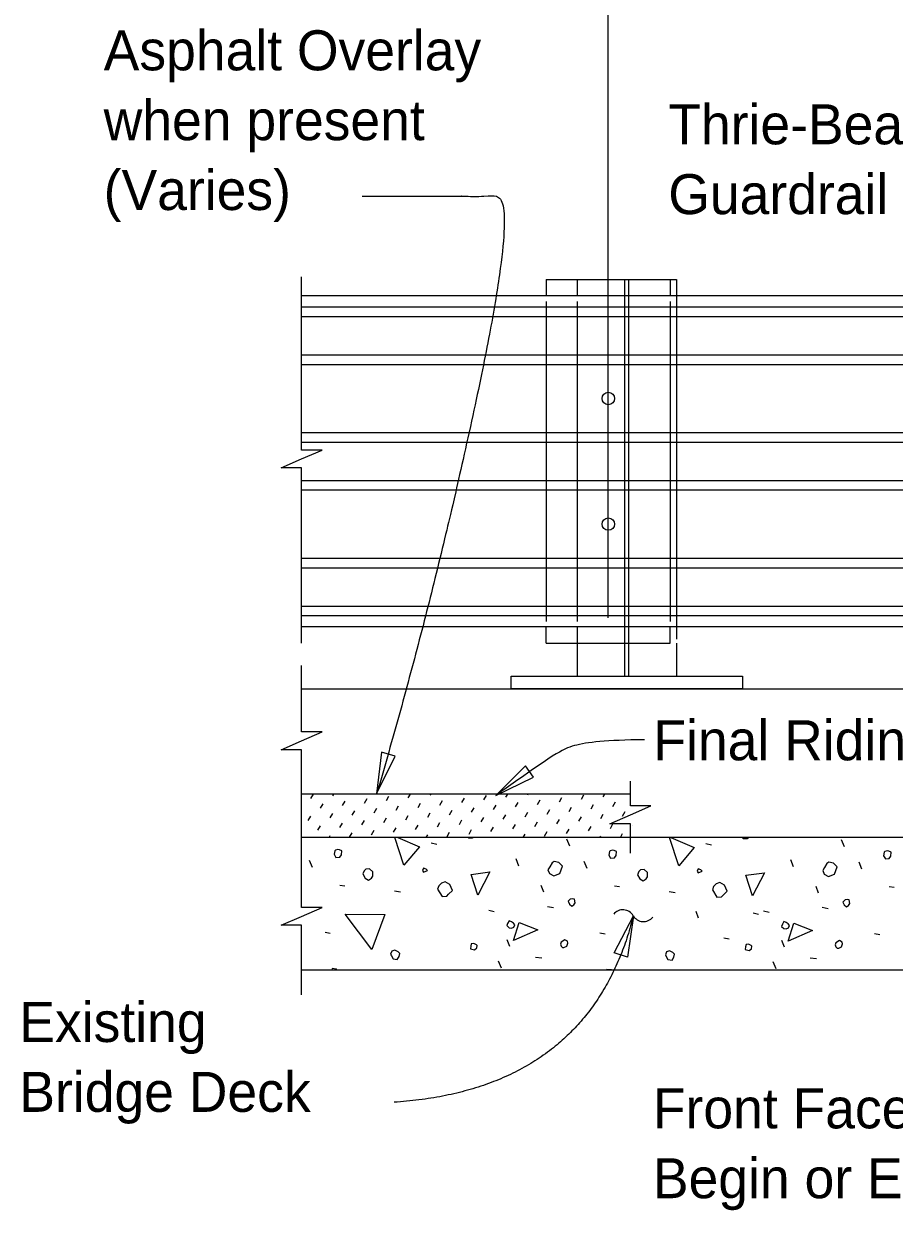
# Model space of a CAD drawing. Extents: x 21587 to 21659.1, y 56113.9 to 56155.9.
# Drawn here: x 21605.91 to 21610.3, y 56132.17 to 56138.15 of the extents above; entities that cross this region are included whole.
import ezdxf

# ---------------------------------------------------------------- set-up
doc = ezdxf.new("R2010")
doc.units = 0
for name, color, linetype in [('AdhocPoint_dp', 7, 'Continuous'), ('Border', 7, 'Continuous'), ('Patterning', 7, 'Continuous'), ('PlotBorder_dp', 7, 'Continuous'), ('SheetBorder_dp', 7, 'Continuous'), ('TextMisc', 7, 'Continuous')]:
    doc.layers.add(name, color=color, linetype=linetype)

msp = doc.modelspace()

# ---------------------------------------------------------------- linework, layer by layer
at = {"layer": 'AdhocPoint_dp'}
for p, q in [((21607.3117, 56134.8009), (21613.4854, 56134.8009)), ((21608.9696, 56134.2699), (21607.3116, 56134.2699)), ((21613.4854, 56134.0509), (21607.3117, 56134.0509)), ((21607.3117, 56133.3843), (21613.4854, 56133.3843))]:
    msp.add_line(p, q, dxfattribs=at)
at = {"layer": 'Border'}
for p, q in [((21608.7018, 56136.8635), (21609.2018, 56136.8635)), ((21608.7018, 56136.8635), (21608.7018, 56136.7802)), ((21619.5663, 56136.7801), (21607.3117, 56136.7801)), ((21607.3117, 56136.7246), (21619.5663, 56136.7246)), ((21607.3117, 56136.6764), (21619.5663, 56136.6764)), ((21607.3117, 56136.4835), (21619.5663, 56136.4835)), ((21607.3117, 56136.4353), (21619.5663, 56136.4353)), ((21607.3117, 56136.0914), (21619.5663, 56136.0914)), ((21607.3117, 56136.0431), (21619.5663, 56136.0431)), ((21607.3117, 56135.8503), (21619.5663, 56135.8503)), ((21607.3117, 56135.8022), (21619.5663, 56135.8022)), ((21607.3117, 56135.4582), (21619.5663, 56135.4582)), ((21607.3117, 56135.41), (21619.5663, 56135.41)), ((21607.3117, 56135.2172), (21619.5663, 56135.2172)), ((21607.3117, 56135.169), (21619.5663, 56135.169)), ((21619.5663, 56135.1134), (21607.3117, 56135.1134)), ((21608.7018, 56135.1135), (21608.7018, 56134.8635)), ((21609.2018, 56135.0302), (21609.2018, 56134.8635)), ((21608.3685, 56134.8635), (21609.5351, 56134.8635)), ((21608.3685, 56134.801), (21608.3685, 56134.8635)), ((21608.7018, 56134.8635), (21609.2018, 56134.8635)), ((21609.5351, 56134.8635), (21609.5351, 56134.801)), ((21608.3685, 56134.801), (21609.5351, 56134.801))]:
    msp.add_line(p, q, dxfattribs=at)
for centre in [(21608.858, 56136.2634), (21608.858, 56135.6303)]:
    msp.add_circle(centre, 0.0312, dxfattribs=at)
at = {"layer": 'Patterning'}
for p, q in [((21608.9414, 56134.8635), (21608.9414, 56136.8635)), ((21608.9622, 56134.8635), (21608.9622, 56136.8635)), ((21609.2018, 56136.8635), (21609.2018, 56135.0505)), ((21608.7018, 56136.7516), (21608.7018, 56135.1398))]:
    msp.add_line(p, q, dxfattribs=at)
at = {"layer": 'PlotBorder_dp'}
msp.add_line((21608.858, 56135.1577), (21608.858, 56143.2258), dxfattribs=at)
for points in [[(21607.3117, 56135.0303), (21607.3117, 56135.9135), (21607.2084, 56135.9135), (21607.3117, 56135.9585), (21607.4151, 56136.0035), (21607.3117, 56136.0035), (21607.3117, 56136.8765)], [(21607.3117, 56134.0229), (21607.3117, 56134.493), (21607.2084, 56134.493), (21607.3117, 56134.538), (21607.4151, 56134.583), (21607.3117, 56134.583), (21607.3117, 56134.9175)], [(21608.9697, 56133.972), (21608.9697, 56134.1198), (21608.8664, 56134.1198), (21608.9697, 56134.1648), (21609.073, 56134.2098), (21608.9697, 56134.2098), (21608.9697, 56134.3343)], [(21607.3117, 56133.2578), (21607.3117, 56133.6084), (21607.2084, 56133.6084), (21607.3117, 56133.6534), (21607.4151, 56133.6984), (21607.3117, 56133.6984), (21607.3117, 56134.0229)]]:
    msp.add_lwpolyline(points, dxfattribs=at)
for points in [[(21607.6902, 56134.2707), (21607.7828, 56134.4606), (21607.7151, 56134.4805)], [(21608.2911, 56134.2633), (21608.4817, 56134.3543), (21608.4411, 56134.412)], [(21608.9843, 56133.6565), (21608.9539, 56133.4475), (21608.8867, 56133.4692)]]:
    msp.add_lwpolyline(points, close=True, dxfattribs=at)
for centre, start, end in [((21608.9319, 56133.6269), 30.00813, 141.73535), ((21609.0352, 56133.6865), 210.00813, 321.73535)]:
    msp.add_arc(centre, 0.0596, start, end, dxfattribs=at)
for points, degree in [([(21607.6165, 56137.2827), (21608.1708, 56137.2827), (21608.4111, 56137.2827), (21607.9729, 56135.2323), (21607.6902, 56134.2708)], 2), ([(21609.0397, 56134.5436), (21608.8463, 56134.5415), (21608.6579, 56134.5211), (21608.5865, 56134.4713), (21608.2911, 56134.2634)], 3), ([(21608.9843, 56133.6565), (21608.7637, 56132.7828), (21607.778, 56132.7162)], 2)]:
    msp.add_open_spline(points, degree=degree, dxfattribs=at)
at = {"layer": 'TextMisc'}
for p, q in [((21608.5455, 56136.8635), (21609.1705, 56136.8635)), ((21608.5455, 56136.8635), (21608.5455, 56136.7802)), ((21609.1705, 56136.8635), (21609.1705, 56136.7802)), ((21608.5455, 56136.7516), (21608.5455, 56135.1398)), ((21609.1705, 56136.7516), (21609.1705, 56135.1398)), ((21608.5455, 56135.0302), (21608.5455, 56135.1135)), ((21609.1705, 56135.0302), (21609.1705, 56135.1135)), ((21608.5455, 56135.0302), (21609.1705, 56135.0302)), ((21607.3586, 56134.2474), (21607.3715, 56134.2698)), ((21607.4692, 56134.2604), (21607.4747, 56134.2699)), ((21607.8499, 56134.2504), (21607.8612, 56134.2699)), ((21607.9606, 56134.2634), (21607.9643, 56134.2699)), ((21608.3413, 56134.2535), (21608.3508, 56134.2699)), ((21608.4519, 56134.2664), (21608.4539, 56134.2699)), ((21608.722, 56134.2435), (21608.735, 56134.2659)), ((21608.8327, 56134.2565), (21608.8404, 56134.2699)), ((21608.9433, 56134.2695), (21608.9436, 56134.2699)), ((21607.4074, 56134.1986), (21607.4204, 56134.221)), ((21607.518, 56134.2116), (21607.531, 56134.234)), ((21607.6287, 56134.2245), (21607.6416, 56134.2469)), ((21607.7393, 56134.2375), (21607.7523, 56134.2599)), ((21607.7881, 56134.1887), (21607.8011, 56134.211)), ((21607.8988, 56134.2016), (21607.9117, 56134.224)), ((21608.0094, 56134.2146), (21608.0224, 56134.237)), ((21608.12, 56134.2275), (21608.133, 56134.2499)), ((21608.2307, 56134.2405), (21608.2436, 56134.2629)), ((21608.2795, 56134.1917), (21608.2925, 56134.2141)), ((21608.3901, 56134.2046), (21608.4031, 56134.227)), ((21608.5008, 56134.2176), (21608.5137, 56134.24)), ((21608.6114, 56134.2306), (21608.6244, 56134.253)), ((21608.6602, 56134.1817), (21608.6732, 56134.2041)), ((21608.7709, 56134.1947), (21608.7838, 56134.2171)), ((21608.8815, 56134.2077), (21608.8945, 56134.23)), ((21607.3456, 56134.1368), (21607.3586, 56134.1592)), ((21607.4562, 56134.1498), (21607.4692, 56134.1722)), ((21607.5669, 56134.1627), (21607.5798, 56134.1851)), ((21607.6775, 56134.1757), (21607.6905, 56134.1981)), ((21607.7263, 56134.1269), (21607.7393, 56134.1492)), ((21607.837, 56134.1398), (21607.8499, 56134.1622)), ((21607.9476, 56134.1528), (21607.9606, 56134.1752)), ((21608.0582, 56134.1657), (21608.0712, 56134.1881)), ((21608.1689, 56134.1787), (21608.1818, 56134.2011)), ((21608.2177, 56134.1299), (21608.2307, 56134.1523)), ((21608.3283, 56134.1428), (21608.3413, 56134.1652)), ((21608.439, 56134.1558), (21608.4519, 56134.1782)), ((21608.5496, 56134.1688), (21608.5626, 56134.1912)), ((21608.7091, 56134.1329), (21608.722, 56134.1553)), ((21608.8197, 56134.1459), (21608.8327, 56134.1682)), ((21608.9303, 56134.1588), (21608.9433, 56134.1812)), ((21607.3944, 56134.088), (21607.4074, 56134.1104)), ((21607.5051, 56134.1009), (21607.518, 56134.1233)), ((21607.6157, 56134.1139), (21607.6287, 56134.1363)), ((21607.6645, 56134.0651), (21607.6775, 56134.0874)), ((21607.7752, 56134.078), (21607.7881, 56134.1004)), ((21607.8858, 56134.091), (21607.8988, 56134.1134)), ((21607.9964, 56134.1039), (21608.0094, 56134.1263)), ((21608.1071, 56134.1169), (21608.12, 56134.1393)), ((21608.1559, 56134.0681), (21608.1689, 56134.0905)), ((21608.2665, 56134.081), (21608.2795, 56134.1034)), ((21608.3772, 56134.094), (21608.3901, 56134.1164)), ((21608.4878, 56134.107), (21608.5008, 56134.1294)), ((21608.5984, 56134.1199), (21608.6114, 56134.1423)), ((21608.6473, 56134.0711), (21608.6602, 56134.0935)), ((21608.7579, 56134.0841), (21608.7709, 56134.1065)), ((21608.8685, 56134.097), (21608.8815, 56134.1194)), ((21608.9792, 56134.11), (21608.9793, 56134.1102)), ((21607.4501, 56134.0509), (21607.4562, 56134.0615)), ((21607.5539, 56134.0521), (21607.5669, 56134.0745)), ((21607.8366, 56134.0509), (21607.837, 56134.0516)), ((21607.9397, 56134.0509), (21607.9476, 56134.0645)), ((21608.0453, 56134.0551), (21608.0582, 56134.0775)), ((21608.3262, 56134.0509), (21608.3283, 56134.0546)), ((21608.4293, 56134.0509), (21608.439, 56134.0676)), ((21608.5366, 56134.0581), (21608.5496, 56134.0805)), ((21608.6635, 56134.0079), (21608.6494, 56134.0432)), ((21608.8158, 56134.0509), (21608.8197, 56134.0576)), ((21608.919, 56134.0509), (21608.9303, 56134.0706)), ((21610.0482, 56134.0043), (21610.034, 56134.0397)), ((21607.9652, 56134.0238), (21607.9935, 56134.0167)), ((21609.3499, 56134.0203), (21609.3782, 56134.0132)), ((21607.3666, 56133.8989), (21607.3524, 56133.9343)), ((21608.4072, 56133.9071), (21608.393, 56133.9425)), ((21608.7513, 56133.8954), (21608.7371, 56133.9307)), ((21609.7919, 56133.9036), (21609.7777, 56133.9389)), ((21610.1359, 56133.8918), (21610.1218, 56133.9272)), ((21607.5045, 56133.8105), (21607.5292, 56133.807)), ((21608.5327, 56133.7745), (21608.5203, 56133.8081)), ((21608.8892, 56133.807), (21608.9139, 56133.8034)), ((21609.9174, 56133.771), (21609.905, 56133.8046)), ((21610.2738, 56133.8034), (21610.2986, 56133.7999)), ((21607.7802, 56133.7822), (21607.8103, 56133.7769)), ((21609.1649, 56133.7787), (21609.195, 56133.7734)), ((21608.2552, 56133.6844), (21608.2834, 56133.6773)), ((21608.5515, 56133.7027), (21608.5816, 56133.6974)), ((21609.3134, 56133.6443), (21609.301, 56133.6779)), ((21609.5874, 56133.6709), (21609.6157, 56133.6638)), ((21609.6398, 56133.6808), (21609.6681, 56133.6738)), ((21609.9362, 56133.6991), (21609.9662, 56133.6938)), ((21607.4302, 56133.5736), (21607.4567, 56133.5683)), ((21608.8149, 56133.5701), (21608.8414, 56133.5648)), ((21610.1996, 56133.5666), (21610.2261, 56133.5613)), ((21608.3612, 56133.5018), (21608.3488, 56133.5354)), ((21609.4407, 56133.5453), (21609.4672, 56133.54)), ((21609.7459, 56133.4982), (21609.7335, 56133.5318)), ((21608.3188, 56133.3922), (21608.3046, 56133.4275)), ((21608.4914, 56133.4481), (21608.5232, 56133.4446)), ((21609.8761, 56133.4446), (21609.9079, 56133.4411)), ((21609.7035, 56133.3886), (21609.6893, 56133.424))]:
    msp.add_line(p, q, dxfattribs=at)
for points in [[(21607.828, 56133.9113), (21607.7825, 56134.0509)], [(21607.7964, 56134.0509), (21607.9058, 56134.0032), (21607.828, 56133.9113)], [(21608.1516, 56134.0509), (21608.1526, 56134.0485), (21608.1502, 56134.0509)], [(21608.1526, 56134.0485), (21608.1738, 56134.0485), (21608.1762, 56134.0509)], [(21609.2127, 56133.9077), (21609.1661, 56134.0509)], [(21609.173, 56134.0509), (21609.2904, 56133.9997), (21609.2127, 56133.9077)], [(21609.5348, 56134.0509), (21609.5373, 56134.045), (21609.5338, 56134.0485)], [(21609.5373, 56134.045), (21609.5585, 56134.045), (21609.5644, 56134.0509)], [(21607.4762, 56133.9661), (21607.485, 56133.9502), (21607.5045, 56133.9519), (21607.5133, 56133.9643), (21607.5151, 56133.9838), (21607.5027, 56133.9891), (21607.4939, 56133.9908), (21607.4833, 56133.9873), (21607.4797, 56133.9838), (21607.4762, 56133.9661)], [(21608.8609, 56133.9625), (21608.8697, 56133.9466), (21608.8892, 56133.9484), (21608.898, 56133.9608), (21608.8998, 56133.9802), (21608.8874, 56133.9855), (21608.8785, 56133.9873), (21608.8679, 56133.9838), (21608.8644, 56133.9802), (21608.8609, 56133.9625)], [(21610.2455, 56133.959), (21610.2544, 56133.9431), (21610.2738, 56133.9449), (21610.2827, 56133.9572), (21610.2844, 56133.9767), (21610.2721, 56133.982), (21610.2632, 56133.9838), (21610.2526, 56133.9802), (21610.2491, 56133.9767), (21610.2455, 56133.959)], [(21608.561, 56133.87), (21608.584, 56133.8576), (21608.614, 56133.87), (21608.6264, 56133.9071), (21608.6087, 56133.9248), (21608.5857, 56133.9301), (21608.5751, 56133.923), (21608.5627, 56133.9036), (21608.5539, 56133.8877), (21608.561, 56133.87)], [(21609.9457, 56133.8665), (21609.9686, 56133.8541), (21609.9987, 56133.8665), (21610.0111, 56133.9036), (21609.9934, 56133.9213), (21609.9704, 56133.9266), (21609.9598, 56133.9195), (21609.9474, 56133.9), (21609.9386, 56133.8841), (21609.9457, 56133.8665)], [(21607.6211, 56133.8671), (21607.6318, 56133.8459), (21607.6494, 56133.8353), (21607.6636, 56133.8459), (21607.6706, 56133.8565), (21607.6706, 56133.8777), (21607.6547, 56133.8936), (21607.6353, 56133.8918), (21607.6265, 56133.883), (21607.6211, 56133.8671)], [(21607.927, 56133.8759), (21607.9464, 56133.8848), (21607.9393, 56133.8918), (21607.927, 56133.8971), (21607.9217, 56133.8848), (21607.927, 56133.8759)], [(21608.2003, 56133.7604), (21608.1668, 56133.8647), (21608.2605, 56133.8771), (21608.2003, 56133.7604)], [(21609.0058, 56133.8635), (21609.0164, 56133.8423), (21609.0341, 56133.8317), (21609.0483, 56133.8423), (21609.0553, 56133.8529), (21609.0553, 56133.8742), (21609.0394, 56133.8901), (21609.02, 56133.8883), (21609.0111, 56133.8795), (21609.0058, 56133.8635)], [(21609.3116, 56133.8724), (21609.3311, 56133.8812), (21609.324, 56133.8883), (21609.3116, 56133.8936), (21609.3063, 56133.8812), (21609.3116, 56133.8724)], [(21609.585, 56133.7569), (21609.5514, 56133.8612), (21609.6451, 56133.8735), (21609.585, 56133.7569)], [(21607.9977, 56133.7911), (21608.0207, 56133.7539), (21608.0436, 56133.7557), (21608.0525, 56133.7646), (21608.0719, 56133.784), (21608.0596, 56133.814), (21608.0348, 56133.8282), (21608.0171, 56133.8211), (21608.003, 56133.807), (21607.9977, 56133.7911)], [(21609.3824, 56133.7875), (21609.4053, 56133.7504), (21609.4283, 56133.7522), (21609.4372, 56133.761), (21609.4566, 56133.7805), (21609.4442, 56133.8105), (21609.4195, 56133.8247), (21609.4018, 56133.8176), (21609.3877, 56133.8034), (21609.3824, 56133.7875)], [(21608.6629, 56133.7151), (21608.6735, 56133.7044), (21608.6841, 56133.7115), (21608.6912, 56133.7221), (21608.6876, 56133.7398), (21608.6788, 56133.7416), (21608.6664, 56133.7398), (21608.6558, 56133.7292), (21608.6629, 56133.7151)], [(21610.0476, 56133.7115), (21610.0582, 56133.7009), (21610.0688, 56133.708), (21610.0758, 56133.7186), (21610.0723, 56133.7363), (21610.0635, 56133.738), (21610.0511, 56133.7363), (21610.0405, 56133.7257), (21610.0476, 56133.7115)], [(21607.6653, 56133.487), (21607.531, 56133.6638), (21607.7307, 56133.662), (21607.6653, 56133.487)], [(21608.3577, 56133.596), (21608.3701, 56133.5942), (21608.3824, 56133.5995), (21608.386, 56133.6101), (21608.3807, 56133.619), (21608.3701, 56133.626), (21608.3577, 56133.6313), (21608.3506, 56133.6172), (21608.3471, 56133.6066), (21608.3577, 56133.596)], [(21608.38, 56133.5312), (21608.4083, 56133.6231), (21608.502, 56133.586), (21608.38, 56133.5312)], [(21609.7424, 56133.5925), (21609.7547, 56133.5907), (21609.7671, 56133.596), (21609.7706, 56133.6066), (21609.7653, 56133.6154), (21609.7547, 56133.6225), (21609.7424, 56133.6278), (21609.7353, 56133.6137), (21609.7318, 56133.6031), (21609.7424, 56133.5925)], [(21609.7647, 56133.5277), (21609.793, 56133.6196), (21609.8867, 56133.5825), (21609.7647, 56133.5277)], [(21608.1639, 56133.4905), (21608.1833, 56133.4852), (21608.1957, 56133.4941), (21608.1974, 56133.5065), (21608.1939, 56133.51), (21608.1798, 56133.5171), (21608.1674, 56133.5153), (21608.1656, 56133.5029), (21608.1639, 56133.4905)], [(21608.6275, 56133.4959), (21608.6346, 56133.4959), (21608.6487, 56133.5029), (21608.654, 56133.5188), (21608.6523, 56133.5277), (21608.6381, 56133.5347), (21608.6205, 56133.5241), (21608.6169, 56133.5135), (21608.6205, 56133.5029), (21608.6275, 56133.4959)], [(21609.5485, 56133.487), (21609.568, 56133.4817), (21609.5803, 56133.4905), (21609.5821, 56133.5029), (21609.5786, 56133.5065), (21609.5644, 56133.5135), (21609.5521, 56133.5118), (21609.5503, 56133.4994), (21609.5485, 56133.487)], [(21610.0122, 56133.4923), (21610.0193, 56133.4923), (21610.0334, 56133.4994), (21610.0387, 56133.5153), (21610.0369, 56133.5241), (21610.0228, 56133.5312), (21610.0051, 56133.5206), (21610.0016, 56133.51), (21610.0051, 56133.4994), (21610.0122, 56133.4923)], [(21607.7643, 56133.4552), (21607.7732, 56133.4393), (21607.7944, 56133.4357), (21607.8032, 56133.4517), (21607.8068, 56133.4658), (21607.7979, 56133.4746), (21607.782, 56133.4835), (21607.7661, 56133.4782), (21607.7608, 56133.4623), (21607.7643, 56133.4552)], [(21609.149, 56133.4517), (21609.1579, 56133.4357), (21609.1791, 56133.4322), (21609.1879, 56133.4481), (21609.1914, 56133.4623), (21609.1826, 56133.4711), (21609.1667, 56133.4799), (21609.1508, 56133.4746), (21609.1455, 56133.4587), (21609.149, 56133.4517)], [(21607.4896, 56133.3843), (21607.4886, 56133.388), (21607.4656, 56133.3898), (21607.4637, 56133.3843)], [(21608.8733, 56133.3843), (21608.8732, 56133.3845), (21608.8503, 56133.3862), (21608.8496, 56133.3843)]]:
    msp.add_lwpolyline(points, dxfattribs=at)

# ---------------------------------------------------------------- texts
at = {"layer": 'PlotBorder_dp'}
for s, p in [('Asphalt Overlay', (21606.3143, 56137.9173)), ('when present', (21606.3143, 56137.5653)), ('Thrie-Beam ', (21609.1604, 56137.5444)), ('(Varies)', (21606.3143, 56137.2133)), ('Guardrail', (21609.1604, 56137.1924)), ('Existing ', (21605.8891, 56133.0202)), ('Bridge Deck', (21605.8891, 56132.6682)), ('Front Face of Backwall &', (21609.0827, 56132.5849)), ('Begin or End Bridge', (21609.0827, 56132.2329))]:
    msp.add_text(s, height=0.2016, dxfattribs=at).set_placement(p)
at = {"layer": 'SheetBorder_dp'}
msp.add_text('Final Riding Surface', height=0.2016, dxfattribs=at).set_placement((21609.0852, 56134.44))

doc.saveas('drawing.dxf')
